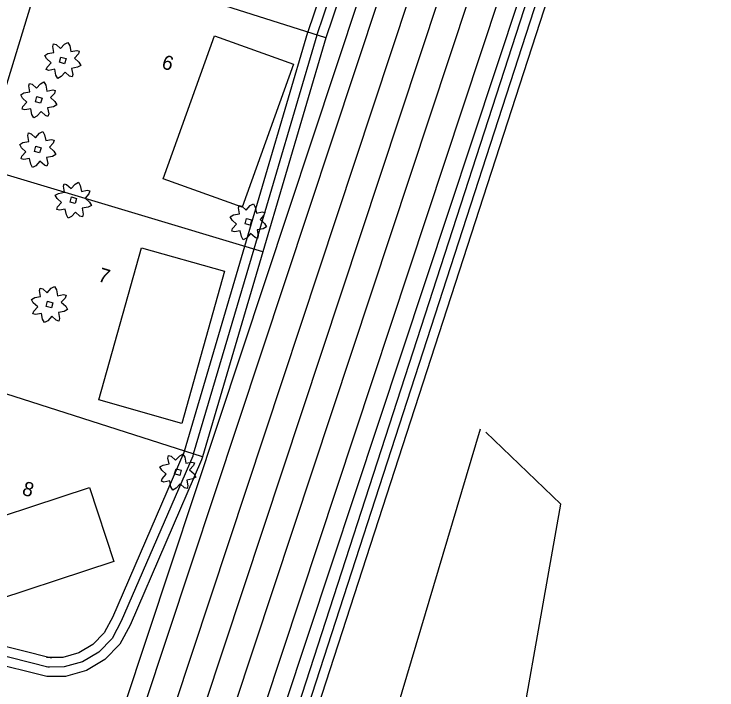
# Model space of a CAD drawing. Extents: x 1810019 to 1811399, y 1074962 to 1076105.
# Drawn here: x 1810639.9 to 1810935.4, y 1075247.7 to 1075531.7 of the extents above; entities that cross this region are included whole.
import ezdxf

# ---------------------------------------------------------------- set-up
doc = ezdxf.new("R2010")
doc.units = 0
for name, color, linetype in [('Environmental-New trees', 7, 'Continuous'), ('Property-Buildings', 7, 'Continuous'), ('Roadway-Centerline main', 7, 'Continuous'), ('Roadway-Edge of pavement', 7, 'Continuous'), ('Roadway-Edge of shoulder', 7, 'Continuous'), ('Roadway-Land lines', 7, 'Continuous'), ('Roadway-Sidewalks', 7, 'Continuous'), ('Text-Property owner', 7, 'Continuous')]:
    doc.layers.add(name, color=color, linetype=linetype)

msp = doc.modelspace()

# ---------------------------------------------------------------- linework, layer by layer
at = {"layer": 'Environmental-New trees'}
for points in [[(1810653.44, 1075508.36), (1810653.75, 1075509.44), (1810655.44, 1075511.3), (1810653.58, 1075513), (1810652.8, 1075514.38), (1810654.15, 1075515.14), (1810656.66, 1075515.64), (1810656.19, 1075518.11), (1810656.49, 1075519.19), (1810657.58, 1075518.88), (1810659.44, 1075517.19), (1810661.13, 1075519.05), (1810662.52, 1075519.83), (1810663.3, 1075518.44), (1810663.77, 1075515.97), (1810666.24, 1075516.44), (1810667.32, 1075516.14), (1810666.95, 1075514.98), (1810665.32, 1075513.19), (1810667.19, 1075511.5), (1810667.96, 1075510.11), (1810666.61, 1075509.35), (1810664.1, 1075508.86), (1810664.58, 1075506.39), (1810664.27, 1075505.31), (1810663.19, 1075505.61), (1810661.33, 1075507.31), (1810659.63, 1075505.44), (1810658.25, 1075504.67), (1810657.47, 1075506.05), (1810657, 1075508.53), (1810654.52, 1075508.05)], [(1810659.6, 1075513.64), (1810661.77, 1075513.03), (1810661.16, 1075510.86), (1810658.99, 1075511.47)], [(1810643.33, 1075491.78), (1810643.64, 1075492.86), (1810645.33, 1075494.72), (1810643.47, 1075496.41), (1810642.69, 1075497.8), (1810644.04, 1075498.56), (1810646.55, 1075499.05), (1810646.08, 1075501.52), (1810646.38, 1075502.61), (1810647.46, 1075502.3), (1810649.33, 1075500.61), (1810651.02, 1075502.47), (1810652.41, 1075503.25), (1810653.19, 1075501.86), (1810653.66, 1075499.39), (1810656.13, 1075499.86), (1810657.21, 1075499.56), (1810656.84, 1075498.4), (1810655.21, 1075496.61), (1810657.08, 1075494.92), (1810657.85, 1075493.53), (1810656.5, 1075492.77), (1810653.99, 1075492.28), (1810654.47, 1075489.81), (1810654.16, 1075488.72), (1810653.08, 1075489.03), (1810651.22, 1075490.72), (1810649.52, 1075488.86), (1810648.14, 1075488.08), (1810647.36, 1075489.47), (1810646.88, 1075491.94), (1810644.41, 1075491.47)], [(1810649.49, 1075497.05), (1810651.66, 1075496.44), (1810651.05, 1075494.28), (1810648.88, 1075494.89)], [(1810642.89, 1075470.91), (1810643.2, 1075472), (1810644.89, 1075473.86), (1810643.03, 1075475.55), (1810642.25, 1075476.94), (1810643.6, 1075477.7), (1810646.11, 1075478.19), (1810645.64, 1075480.66), (1810645.94, 1075481.75), (1810647.03, 1075481.44), (1810648.89, 1075479.75), (1810650.58, 1075481.61), (1810651.97, 1075482.39), (1810652.75, 1075481), (1810653.22, 1075478.53), (1810655.69, 1075479), (1810656.77, 1075478.69), (1810656.4, 1075477.54), (1810654.78, 1075475.75), (1810656.64, 1075474.06), (1810657.41, 1075472.67), (1810656.06, 1075471.91), (1810653.55, 1075471.42), (1810654.03, 1075468.95), (1810653.72, 1075467.86), (1810652.64, 1075468.17), (1810650.78, 1075469.86), (1810649.08, 1075468), (1810647.7, 1075467.22), (1810646.92, 1075468.61), (1810646.45, 1075471.08), (1810643.97, 1075470.61)], [(1810649.05, 1075476.19), (1810651.22, 1075475.58), (1810650.61, 1075473.42), (1810648.44, 1075474.03)], [(1810657.86, 1075449.6), (1810658.17, 1075450.68), (1810659.86, 1075452.54), (1810658, 1075454.23), (1810657.22, 1075455.62), (1810658.58, 1075456.38), (1810661.08, 1075456.87), (1810660.61, 1075459.34), (1810660.92, 1075460.43), (1810662, 1075460.12), (1810663.86, 1075458.43), (1810665.55, 1075460.29), (1810666.94, 1075461.07), (1810667.72, 1075459.68), (1810668.19, 1075457.21), (1810670.66, 1075457.68), (1810671.75, 1075457.38), (1810671.38, 1075456.22), (1810669.75, 1075454.43), (1810671.61, 1075452.74), (1810672.39, 1075451.35), (1810671.03, 1075450.59), (1810668.53, 1075450.1), (1810669, 1075447.63), (1810668.69, 1075446.54), (1810667.61, 1075446.85), (1810665.75, 1075448.54), (1810664.06, 1075446.68), (1810662.67, 1075445.9), (1810661.89, 1075447.29), (1810661.42, 1075449.76), (1810658.95, 1075449.29)], [(1810664.03, 1075454.87), (1810666.19, 1075454.26), (1810665.58, 1075452.1), (1810663.42, 1075452.71)], [(1810731.45, 1075440.52), (1810731.76, 1075441.61), (1810733.45, 1075443.47), (1810731.59, 1075445.16), (1810730.81, 1075446.55), (1810732.16, 1075447.31), (1810734.67, 1075447.8), (1810734.2, 1075450.27), (1810734.5, 1075451.35), (1810735.59, 1075451.05), (1810737.45, 1075449.36), (1810739.14, 1075451.22), (1810740.53, 1075451.99), (1810741.31, 1075450.61), (1810741.78, 1075448.13), (1810744.25, 1075448.61), (1810745.33, 1075448.3), (1810744.96, 1075447.15), (1810743.33, 1075445.36), (1810745.2, 1075443.66), (1810745.97, 1075442.28), (1810744.62, 1075441.52), (1810742.11, 1075441.03), (1810742.59, 1075438.55), (1810742.28, 1075437.47), (1810741.2, 1075437.78), (1810739.34, 1075439.47), (1810737.64, 1075437.61), (1810736.26, 1075436.83), (1810735.48, 1075438.22), (1810735.01, 1075440.69), (1810732.53, 1075440.22)], [(1810737.61, 1075445.8), (1810739.78, 1075445.19), (1810739.17, 1075443.02), (1810737, 1075443.63)], [(1810647.85, 1075405.78), (1810648.16, 1075406.87), (1810649.85, 1075408.73), (1810647.99, 1075410.42), (1810647.21, 1075411.81), (1810648.56, 1075412.57), (1810651.07, 1075413.06), (1810650.6, 1075415.53), (1810650.9, 1075416.61), (1810651.99, 1075416.31), (1810653.85, 1075414.61), (1810655.54, 1075416.48), (1810656.93, 1075417.25), (1810657.71, 1075415.87), (1810658.18, 1075413.39), (1810660.65, 1075413.87), (1810661.73, 1075413.56), (1810661.36, 1075412.41), (1810659.73, 1075410.62), (1810661.6, 1075408.92), (1810662.37, 1075407.54), (1810661.02, 1075406.78), (1810658.51, 1075406.29), (1810658.99, 1075403.81), (1810658.68, 1075402.73), (1810657.6, 1075403.04), (1810655.74, 1075404.73), (1810654.04, 1075402.87), (1810652.66, 1075402.09), (1810651.88, 1075403.48), (1810651.41, 1075405.95), (1810648.93, 1075405.48)], [(1810654.01, 1075411.06), (1810656.18, 1075410.45), (1810655.57, 1075408.28), (1810653.4, 1075408.89)], [(1810701.83, 1075335.39), (1810702.14, 1075336.47), (1810703.83, 1075338.33), (1810701.97, 1075340.03), (1810701.19, 1075341.42), (1810702.54, 1075342.17), (1810705.05, 1075342.67), (1810704.58, 1075345.14), (1810704.88, 1075346.22), (1810705.97, 1075345.92), (1810707.83, 1075344.22), (1810709.52, 1075346.08), (1810710.91, 1075346.86), (1810711.69, 1075345.47), (1810712.16, 1075343), (1810714.63, 1075343.47), (1810715.71, 1075343.17), (1810715.34, 1075342.01), (1810713.72, 1075340.22), (1810715.58, 1075338.53), (1810716.35, 1075337.14), (1810715, 1075336.39), (1810712.49, 1075335.89), (1810712.97, 1075333.42), (1810712.66, 1075332.34), (1810711.58, 1075332.64), (1810709.72, 1075334.34), (1810708.02, 1075332.48), (1810706.64, 1075331.7), (1810705.86, 1075333.09), (1810705.39, 1075335.56), (1810702.91, 1075335.08)], [(1810707.99, 1075340.67), (1810710.16, 1075340.06), (1810709.55, 1075337.89), (1810707.38, 1075338.5)]]:
    msp.add_lwpolyline(points, close=True, dxfattribs=at)
msp.add_lwpolyline([(1810835.88, 1075357.27), (1810791.12, 1075207.25), (1810749.98, 1075091.1), (1810808.06, 1075070.54), (1811029.46, 1075075.38), (1811082.69, 1075091.1), (1811029.46, 1075114.09), (1810862.5, 1075116.51), (1810845.56, 1075189.1), (1810869.76, 1075325.81), (1810838.3, 1075356.06)], dxfattribs=at)
at = {"layer": 'Property-Buildings'}
for points in [[(1810757.31, 1075510.67), (1810735.81, 1075450.58), (1810702.64, 1075462.46), (1810724.15, 1075522.54)], [(1810728.4, 1075423.66), (1810710.39, 1075359.74), (1810675.5, 1075369.57), (1810693.51, 1075433.5)], [(1810681.82, 1075301.73), (1810621.28, 1075281.84), (1810611.09, 1075312.85), (1810671.63, 1075332.75)]]:
    msp.add_lwpolyline(points, close=True, dxfattribs=at)
at = {"layer": 'Roadway-Centerline main'}
msp.add_line((1811006.18, 1076104.35), (1810632.15, 1074976.37), dxfattribs=at)
at = {"layer": 'Roadway-Edge of pavement'}
for p, q in [((1811018.91, 1076104.62), (1810645.22, 1074977.65)), ((1811031.64, 1076104.89), (1810658.29, 1074978.93)), ((1810980.71, 1076103.81), (1810606.02, 1074973.81)), ((1810993.45, 1076104.08), (1810619.08, 1074975.09))]:
    msp.add_line(p, q, dxfattribs=at)
at = {"layer": 'Roadway-Edge of shoulder'}
for p, q in [((1811040.13, 1076105.07), (1810667, 1074979.79)), ((1810972.23, 1076103.63), (1810597.31, 1074972.96))]:
    msp.add_line(p, q, dxfattribs=at)
at = {"layer": 'Roadway-Land lines'}
for p, q in [((1810946.95, 1075819.07), (1810694.59, 1075041.79)), ((1810800.18, 1075609.17), (1810771, 1075521.77)), ((1810626.09, 1075467.25), (1810654.04, 1075558.89)), ((1810771, 1075521.77), (1810654.04, 1075558.89)), ((1810771, 1075521.77), (1810744.49, 1075431.86)), ((1810744.49, 1075431.86), (1810626.09, 1075467.25)), ((1810744.49, 1075431.86), (1810719.05, 1075345.61)), ((1810719.05, 1075345.61), (1810600.6, 1075383.71)), ((1810719.05, 1075345.61), (1810718.69, 1075344.36)), ((1810718.69, 1075344.36), (1810688.64, 1075274.97))]:
    msp.add_line(p, q, dxfattribs=at)
for points in [[(1810688.64, 1075274.97), (1810684.35, 1075267), (1810678.09, 1075260.45), (1810670.31, 1075255.82), (1810661.58, 1075253.43), (1810653.65, 1075253.31)], [(1810653.65, 1075253.31), (1810628.78, 1075259.52), (1810603.1, 1075265.03), (1810571.04, 1075270.55)]]:
    msp.add_lwpolyline(points, dxfattribs=at)
at = {"layer": 'Roadway-Sidewalks'}
for p, q in [((1810949.56, 1075814.15), (1810700.07, 1075045.72)), ((1810952.49, 1075810.24), (1810705.56, 1075049.66)), ((1810792.59, 1075611.71), (1810763.42, 1075524.3)), ((1810796.38, 1075610.44), (1810767.21, 1075523.03)), ((1810763.33, 1075524.03), (1810736.82, 1075434.12)), ((1810767.17, 1075522.9), (1810740.65, 1075432.99)), ((1810736.82, 1075434.12), (1810711.38, 1075347.87)), ((1810740.65, 1075432.99), (1810715.22, 1075346.74)), ((1810711.34, 1075347.54), (1810681.3, 1075278.15)), ((1810715.02, 1075345.95), (1810684.97, 1075276.56)), ((1810711.38, 1075347.88), (1810711.01, 1075346.63)), ((1810715.22, 1075346.74), (1810714.85, 1075345.5))]:
    msp.add_line(p, q, dxfattribs=at)
for points in [[(1810655.59, 1075261.07), (1810630.59, 1075267.32), (1810604.61, 1075272.89), (1810572.4, 1075278.43)], [(1810681.59, 1075278.76), (1810677.82, 1075271.74), (1810673.06, 1075266.77), (1810667.15, 1075263.25), (1810660.45, 1075261.41), (1810653.54, 1075261.31)], [(1810654.62, 1075257.19), (1810629.69, 1075263.42), (1810603.85, 1075268.96), (1810571.72, 1075274.49)], [(1810685.12, 1075276.86), (1810681.09, 1075269.37), (1810675.58, 1075263.61), (1810668.73, 1075259.53), (1810661.01, 1075257.42), (1810653.6, 1075257.31)]]:
    msp.add_lwpolyline(points, dxfattribs=at)

# ---------------------------------------------------------------- texts
at = {"layer": 'Text-Property owner'}
for s, p in [('6', (1810701.57, 1075509.03)), ('7', (1810674.85, 1075419.58)), ('8', (1810642.88, 1075329.87))]:
    msp.add_text(s, height=6, rotation=343.3561, dxfattribs=at).set_placement(p)

doc.saveas('drawing.dxf')
